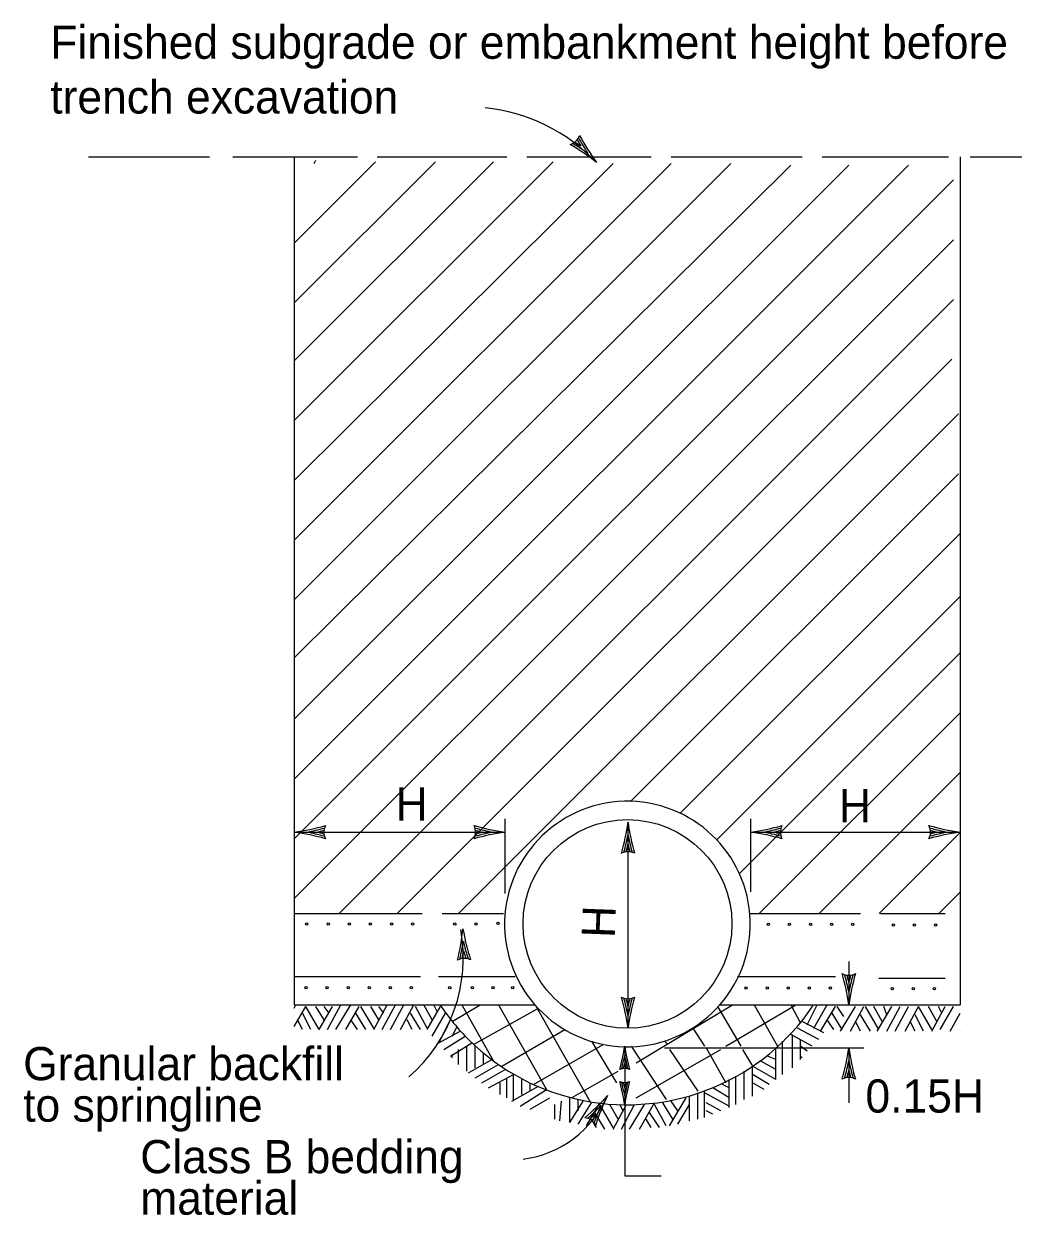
# Model space of a CAD drawing. Extents: x 0 to 390, y 0 to 265.
# Drawn here: x 74.8 to 134.4, y 108.9 to 180.6 of the extents above; entities that cross this region are included whole.
import ezdxf

# ---------------------------------------------------------------- set-up
doc = ezdxf.new("R2010")
doc.units = 0
doc.layers.add('D_Details', color=7, linetype='Continuous')

msp = doc.modelspace()

# ---------------------------------------------------------------- linework, layer by layer
at = {"layer": 'D_Details'}
for p, q in [((78.717, 172.634), (86.017, 172.634)), ((87.417, 172.634), (94.917, 172.634)), ((91.117, 172.634), (91.117, 121.534)), ((91.117, 167.434), (96.017, 172.334)), ((91.117, 163.834), (99.617, 172.334)), ((91.117, 160.334), (103.117, 172.334)), ((91.117, 156.734), (106.717, 172.334)), ((92.317, 172.234), (92.417, 172.434)), ((96.117, 172.634), (103.917, 172.634)), ((105.117, 172.634), (112.617, 172.634)), ((113.817, 172.634), (121.717, 172.634)), ((122.917, 172.634), (130.517, 172.634)), ((131.217, 172.634), (131.217, 121.534)), ((131.817, 172.634), (139.417, 172.634)), ((91.117, 153.134), (110.317, 172.234)), ((91.117, 149.534), (113.817, 172.234)), ((91.117, 145.934), (117.417, 172.234)), ((91.117, 142.434), (121.017, 172.134)), ((91.117, 138.734), (124.517, 172.134)), ((91.117, 135.134), (128.117, 172.134)), ((91.117, 131.534), (130.817, 171.234)), ((91.117, 127.934), (130.817, 167.634)), ((93.817, 127.034), (130.817, 164.034)), ((97.317, 127.034), (130.717, 160.434)), ((101.017, 127.034), (131.117, 157.134)), ((111.375, 133.792), (131.117, 153.534)), ((114.36, 133.077), (131.217, 149.934)), ((116.559, 131.476), (131.217, 146.134)), ((117.923, 129.44), (131.217, 142.734)), ((119.124, 127.034), (131.217, 139.127)), ((122.73, 127.034), (131.217, 135.521)), ((103.817, 128.234), (103.817, 132.734)), ((111.217, 120.118), (111.217, 132.534)), ((118.617, 128.334), (118.617, 132.734)), ((91.117, 131.934), (103.817, 131.934)), ((118.617, 131.934), (131.217, 131.934)), ((126.336, 127.034), (131.217, 131.915)), ((129.942, 127.034), (131.217, 128.309)), ((91.117, 127.034), (98.817, 127.034)), ((100.017, 127.034), (103.717, 127.034)), ((118.517, 127.034), (125.217, 127.034)), ((126.417, 127.034), (130.317, 127.034)), ((124.517, 124.134), (124.517, 121.534)), ((91.117, 123.234), (98.717, 123.234)), ((99.809, 123.234), (104.417, 123.234)), ((117.817, 123.234), (123.717, 123.234)), ((126.317, 123.134), (130.317, 123.134)), ((91.117, 121.534), (105.617, 121.534)), ((91.117, 121.334), (91.217, 121.534)), ((91.117, 120.234), (91.817, 121.434)), ((92.617, 120.034), (91.817, 121.434)), ((92.917, 120.634), (92.417, 121.434)), ((92.617, 120.034), (93.417, 121.434)), ((93.217, 121.034), (92.917, 121.434)), ((93.117, 120.034), (93.917, 121.534)), ((93.417, 121.534), (93.417, 121.534)), ((93.617, 120.034), (94.517, 121.534)), ((94.217, 120.034), (95.017, 121.434)), ((95.917, 120.134), (95.117, 121.434)), ((96.217, 120.634), (95.717, 121.434)), ((95.917, 120.034), (96.717, 121.534)), ((96.517, 121.034), (96.217, 121.434)), ((96.417, 120.034), (97.217, 121.534)), ((96.917, 120.034), (97.717, 121.534)), ((97.517, 120.034), (98.317, 121.534)), ((99.117, 120.134), (98.417, 121.434)), ((99.417, 120.634), (98.917, 121.534)), ((99.117, 120.034), (99.917, 121.434)), ((99.717, 121.134), (99.517, 121.534)), ((100.617, 120.534), (102.317, 121.534)), ((101.217, 121.534), (103.117, 118.134)), ((101.917, 119.134), (105.817, 121.334)), ((103.417, 121.534), (106.317, 116.434)), ((105.617, 121.534), (108.917, 115.734)), ((111.717, 118.034), (117.517, 121.534)), ((116.617, 121.434), (118.017, 119.034)), ((116.717, 121.534), (131.217, 121.534)), ((117.117, 119.034), (121.317, 121.534)), ((118.817, 121.534), (120.217, 119.034)), ((121.017, 121.534), (121.617, 120.434)), ((122.017, 120.334), (122.617, 121.534)), ((122.117, 121.534), (122.117, 121.534)), ((122.417, 120.134), (123.217, 121.534)), ((122.817, 119.934), (123.717, 121.434)), ((123.717, 121.434), (123.717, 121.434)), ((124.217, 120.834), (123.817, 121.434)), ((124.017, 119.934), (124.917, 121.434)), ((124.617, 119.934), (125.417, 121.434)), ((126.317, 120.034), (125.517, 121.434)), ((126.517, 120.534), (126.017, 121.434)), ((126.217, 119.934), (127.117, 121.434)), ((126.817, 120.934), (126.617, 121.434)), ((126.817, 119.934), (127.617, 121.434)), ((127.317, 119.934), (128.117, 121.434)), ((127.917, 119.934), (128.717, 121.434)), ((129.517, 120.034), (128.717, 121.434)), ((129.817, 120.534), (129.317, 121.434)), ((129.517, 119.934), (130.317, 121.434)), ((130.117, 121.034), (129.917, 121.434)), ((130.017, 120.034), (130.817, 121.434)), ((91.617, 120.034), (91.317, 120.634)), ((92.117, 120.034), (91.617, 121.034)), ((94.917, 120.034), (94.517, 120.634)), ((95.417, 120.034), (94.817, 121.034)), ((98.217, 120.034), (97.917, 120.634)), ((98.717, 120.034), (98.117, 121.034)), ((99.417, 119.634), (100.217, 121.034)), ((99.817, 119.234), (100.517, 120.634)), ((123.617, 120.034), (123.217, 120.634)), ((124.117, 120.034), (123.517, 121.034)), ((125.817, 119.934), (125.217, 120.934)), ((129.017, 119.934), (128.517, 120.934)), ((130.617, 119.934), (131.217, 121.034)), ((99.817, 119.234), (101.117, 119.934)), ((100.617, 119.634), (100.917, 120.234)), ((103.617, 117.834), (107.417, 120.034)), ((115.117, 120.134), (115.817, 119.034)), ((122.717, 119.434), (121.417, 120.134)), ((123.017, 119.834), (121.717, 120.534)), ((125.217, 119.934), (124.917, 120.534)), ((128.517, 119.934), (128.217, 120.534)), ((131.217, 119.934), (131.217, 119.934)), ((100.017, 119.834), (100.017, 119.834)), ((100.117, 118.834), (101.417, 119.634)), ((100.517, 118.434), (101.817, 119.234)), ((109.017, 119.334), (110.517, 116.834)), ((113.417, 119.334), (113.617, 119.134)), ((120.517, 117.334), (120.517, 119.334)), ((122.317, 119.034), (121.017, 119.734)), ((121.117, 117.734), (121.117, 119.734)), ((121.617, 118.234), (121.617, 119.434)), ((100.617, 118.334), (100.617, 118.534)), ((101.017, 117.934), (101.017, 118.834)), ((101.517, 117.534), (101.517, 119.034)), ((102.017, 117.734), (102.017, 119.034)), ((102.517, 117.934), (102.517, 118.634)), ((105.517, 116.734), (109.717, 119.134)), ((111.017, 119.034), (111.017, 115.508)), ((111.417, 119.034), (113.517, 115.834)), ((111.717, 115.934), (116.817, 118.834)), ((113.417, 118.934), (125.417, 118.934)), ((113.717, 118.834), (115.417, 116.334)), ((115.917, 118.934), (117.117, 116.834)), ((118.117, 118.834), (118.717, 117.834)), ((120.117, 117.034), (120.117, 118.934)), ((122.017, 118.734), (121.617, 119.034)), ((124.517, 118.934), (124.517, 115.634)), ((101.617, 117.434), (103.017, 118.234)), ((102.017, 117.134), (103.417, 117.934)), ((118.717, 116.034), (118.717, 117.834)), ((120.117, 117.034), (118.717, 117.834)), ((120.117, 117.634), (119.217, 118.134)), ((120.117, 118.234), (119.617, 118.434)), ((121.717, 118.334), (121.617, 118.434)), ((102.417, 116.834), (103.817, 117.634)), ((102.817, 116.534), (104.317, 117.334)), ((103.917, 115.934), (103.917, 117.134)), ((104.317, 115.734), (104.317, 117.334)), ((104.817, 116.134), (104.817, 117.034)), ((107.817, 115.934), (110.617, 117.534)), ((117.317, 115.334), (117.317, 117.034)), ((117.717, 115.534), (117.717, 117.234)), ((118.217, 115.834), (118.217, 117.534)), ((119.717, 116.734), (118.717, 117.334)), ((103.517, 116.134), (103.517, 116.834)), ((104.217, 115.734), (105.817, 116.634)), ((104.717, 115.434), (106.317, 116.434)), ((105.317, 116.334), (105.317, 116.834)), ((115.817, 114.734), (115.817, 116.334)), ((117.317, 115.934), (116.317, 116.534)), ((117.317, 116.534), (116.917, 116.734)), ((119.417, 116.434), (118.717, 116.834)), ((105.317, 115.234), (106.517, 115.934)), ((107.117, 114.534), (107.217, 115.734)), ((107.717, 114.434), (107.717, 115.934)), ((107.717, 114.434), (108.517, 115.734)), ((108.217, 115.134), (108.217, 115.834)), ((108.217, 114.334), (109.017, 115.634)), ((108.717, 114.234), (109.517, 115.634)), ((111.917, 114.034), (112.817, 115.634)), ((113.917, 114.634), (113.317, 115.634)), ((113.717, 114.234), (114.717, 115.934)), ((114.217, 115.134), (113.817, 115.734)), ((114.917, 114.534), (114.917, 116.034)), ((115.417, 114.634), (115.417, 116.234)), ((117.317, 115.434), (115.817, 116.234)), ((116.817, 115.134), (115.917, 115.634)), ((106.817, 114.634), (106.817, 115.534)), ((107.817, 115.534), (107.817, 115.534)), ((109.817, 114.034), (109.217, 115.034)), ((110.317, 114.134), (109.517, 115.534)), ((110.617, 114.634), (110.117, 115.534)), ((110.317, 114.034), (111.117, 115.534)), ((110.917, 115.134), (110.717, 115.534)), ((110.817, 114.034), (111.617, 115.534)), ((111.017, 115.508), (111.017, 111.234)), ((111.317, 114.034), (112.217, 115.534)), ((113.117, 114.134), (112.517, 115.034)), ((113.517, 114.234), (112.817, 115.534)), ((114.217, 114.334), (114.917, 115.534)), ((114.417, 115.334), (114.417, 115.334)), ((116.317, 114.934), (115.917, 115.134)), ((109.317, 114.134), (109.017, 114.634)), ((112.617, 114.134), (112.317, 114.634)), ((111.017, 111.234), (113.217, 111.234))]:
    msp.add_line(p, q, dxfattribs=at)
for centre, radius in [((111.187, 126.405), 6.287), ((91.863, 126.404), 0.0707), ((93.166, 126.404), 0.0707), ((94.436, 126.404), 0.0707), ((95.706, 126.404), 0.0707), ((96.976, 126.404), 0.0707), ((98.246, 126.404), 0.0707), ((100.786, 126.404), 0.0707), ((102.056, 126.404), 0.0707), ((103.377, 126.446), 0.0707), ((119.674, 126.376), 0.0707), ((120.944, 126.376), 0.0707), ((122.214, 126.376), 0.0707), ((123.484, 126.376), 0.0707), ((124.754, 126.376), 0.0707), ((127.201, 126.333), 0.0707), ((128.471, 126.333), 0.0707), ((129.741, 126.333), 0.0707), ((91.825, 122.566), 0.0707), ((93.095, 122.566), 0.0707), ((94.365, 122.566), 0.0707), ((95.635, 122.566), 0.0707), ((96.905, 122.566), 0.0707), ((98.175, 122.566), 0.0707), ((100.485, 122.566), 0.0707), ((101.846, 122.566), 0.0707), ((103.08, 122.566), 0.0707), ((104.271, 122.566), 0.0707), ((118.333, 122.538), 0.0707), ((119.603, 122.538), 0.0707), ((120.873, 122.538), 0.0707), ((122.143, 122.538), 0.0707), ((123.413, 122.538), 0.0707), ((127.13, 122.495), 0.0707), ((128.4, 122.495), 0.0707), ((129.67, 122.495), 0.0707)]:
    msp.add_circle(centre, radius, dxfattribs=at)
for centre, radius, start, end in [((101.454, 164.761), 10.886, 43.76861, 83.9378), ((107.479, 174.209), 0.874, 286.98362, 340.55361), ((120.726, 180.511), 14.188, 208.33854, 212.76762), ((120.726, 180.511), 14.063, 207.95514, 215.76861), ((100.613, 161.245), 14.063, 51.76861, 59.5803), ((100.613, 161.245), 14.188, 54.76961, 59.19869), ((100.613, 161.245), 14.313, 57.12798, 58.93954), ((120.726, 180.511), 14.313, 208.59769, 210.40925), ((111.181, 126.398), 7.397, 1.52094, 1.35499), ((89.16, 145.86), 14.063, 278, 285.81169), ((89.16, 145.86), 14.188, 281.00099, 285.43008), ((93.772, 131.934), 0.874, 153.215, 206.78499), ((105.774, 145.86), 14.063, 254.18653, 262), ((101.162, 131.934), 0.874, 333.215, 26.78499), ((105.774, 145.86), 14.188, 254.56992, 258.99901), ((97.291, 134.491), 14.063, 344.18653, 352), ((125.143, 134.491), 14.063, 188, 195.81169), ((116.66, 145.86), 14.063, 278, 285.81169), ((116.66, 145.86), 14.188, 281.00099, 285.43008), ((121.272, 131.934), 0.874, 153.215, 206.78499), ((133.174, 145.86), 14.063, 254.18653, 262), ((128.562, 131.934), 0.874, 333.215, 26.78499), ((133.174, 145.86), 14.188, 254.56992, 258.99901), ((89.16, 118.009), 14.063, 74.18653, 82), ((89.16, 118.009), 14.188, 74.56992, 78.99901), ((89.16, 145.86), 14.313, 283.35937, 285.17092), ((89.16, 118.009), 14.313, 74.82908, 76.64064), ((105.774, 118.009), 14.063, 98, 105.81169), ((105.774, 118.009), 14.188, 101.00099, 105.43008), ((105.774, 145.86), 14.313, 254.82908, 256.64064), ((105.774, 118.009), 14.313, 103.35937, 105.17092), ((97.291, 134.491), 14.188, 344.56992, 348.99901), ((125.143, 134.491), 14.188, 191.00099, 195.43008), ((116.66, 118.009), 14.063, 74.18653, 82), ((116.66, 118.009), 14.188, 74.56992, 78.99901), ((116.66, 145.86), 14.313, 283.35937, 285.17092), ((116.66, 118.009), 14.313, 74.82908, 76.64064), ((133.174, 118.009), 14.063, 98, 105.81169), ((133.174, 118.009), 14.188, 101.00099, 105.43008), ((133.174, 145.86), 14.313, 254.82908, 256.64064), ((133.174, 118.009), 14.313, 103.35937, 105.17092), ((111.217, 129.879), 0.874, 63.215, 116.78499), ((97.291, 134.491), 14.313, 344.82908, 346.64064), ((125.143, 134.491), 14.313, 193.35937, 195.17092), ((91.773, 124.371), 9.52, 310.98589, 10.30179), ((87.295, 127.614), 14.063, 346.04842, 353.86189), ((115.132, 128.519), 14.063, 189.86189, 197.67357), ((87.295, 127.614), 14.188, 346.43181, 350.86089), ((115.132, 128.519), 14.188, 192.86288, 197.29197), ((101.363, 123.456), 0.874, 65.07689, 118.64688), ((87.295, 127.614), 14.313, 346.69097, 348.50253), ((115.132, 128.519), 14.313, 195.22126, 197.03281), ((110.591, 119.577), 14.063, 8, 15.81169), ((124.517, 124.189), 0.874, 243.215, 296.78499), ((110.591, 119.577), 14.188, 11.00099, 15.43008), ((110.591, 119.577), 14.313, 13.35937, 15.17092), ((138.443, 119.577), 14.188, 164.56992, 168.99901), ((138.443, 119.577), 14.063, 164.18653, 172), ((138.443, 119.577), 14.313, 164.82908, 166.64064), ((111.148, 129.034), 13.526, 213.86279, 225.14782), ((97.291, 118.161), 14.063, 8, 15.81169), ((111.217, 122.773), 0.874, 243.215, 296.78499), ((97.291, 118.161), 14.188, 11.00099, 15.43008), ((97.291, 118.161), 14.313, 13.35937, 15.17092), ((125.143, 118.161), 14.188, 164.56992, 168.99901), ((125.143, 118.161), 14.063, 164.18653, 172), ((125.143, 118.161), 14.313, 164.82908, 166.64064), ((111.148, 129.034), 13.526, 292.85319, 325.97997), ((111.148, 129.034), 13.526, 225.15037, 292.84251), ((100.573, 120.502), 10.547, 344.18653, 352), ((100.573, 120.502), 10.641, 344.56992, 348.99901), ((121.461, 120.502), 10.641, 191.00099, 195.43008), ((121.461, 120.502), 10.547, 188, 195.81169), ((110.591, 120.891), 14.063, 344.18653, 352), ((138.443, 120.891), 14.063, 188, 195.81169), ((100.573, 120.502), 10.734, 344.82908, 346.64064), ((121.461, 120.502), 10.734, 193.35937, 195.17092), ((110.591, 120.891), 14.188, 344.56992, 348.99901), ((138.443, 120.891), 14.188, 191.00099, 195.43008), ((111.017, 117.043), 0.655, 63.215, 116.78499), ((124.517, 116.279), 0.874, 63.215, 116.78499), ((110.591, 120.891), 14.313, 344.82908, 346.64064), ((138.443, 120.891), 14.313, 193.35937, 195.17092), ((100.573, 114.04), 10.547, 8, 15.81169), ((111.017, 117.499), 0.655, 243.215, 296.78499), ((100.573, 114.04), 10.641, 11.00099, 15.43008), ((100.573, 114.04), 10.734, 13.35937, 15.17092), ((121.461, 114.04), 10.641, 164.56992, 168.99901), ((121.461, 114.04), 10.547, 164.18653, 172), ((121.461, 114.04), 10.734, 164.82908, 166.64064), ((104.085, 118.603), 6.419, 277.38287, 336.69876), ((99.461, 125.396), 14.063, 310.60811, 318.42158), ((122.664, 109.992), 14.063, 154.42158, 162.23327), ((99.461, 125.396), 14.188, 310.9915, 315.42059), ((99.461, 125.396), 14.313, 311.25066, 313.06222), ((122.664, 109.992), 14.313, 159.78095, 161.5925), ((122.664, 109.992), 14.188, 157.42258, 161.85166), ((108.512, 113.852), 0.874, 29.63658, 83.20657)]:
    msp.add_arc(centre, radius, start, end, dxfattribs=at)

# ---------------------------------------------------------------- texts
for s, p in [('Finished subgrade or embankment height before', (76.419, 178.536)), ('trench excavation', (76.419, 175.236)), ('H', (97.219, 132.636)), ('H', (123.919, 132.536)), ('Granular backfill', (74.786, 116.988)), ('0.15H', (125.519, 115.036)), ('to springline', (74.786, 114.488)), ('Class B bedding', (81.838, 111.384)), ('material', (81.838, 108.884))]:
    msp.add_text(s, height=2, dxfattribs=at).set_placement(p)
msp.add_text('H', height=2, rotation=87.83705, dxfattribs=at).set_placement((110.419, 125.536))

doc.saveas('drawing.dxf')
